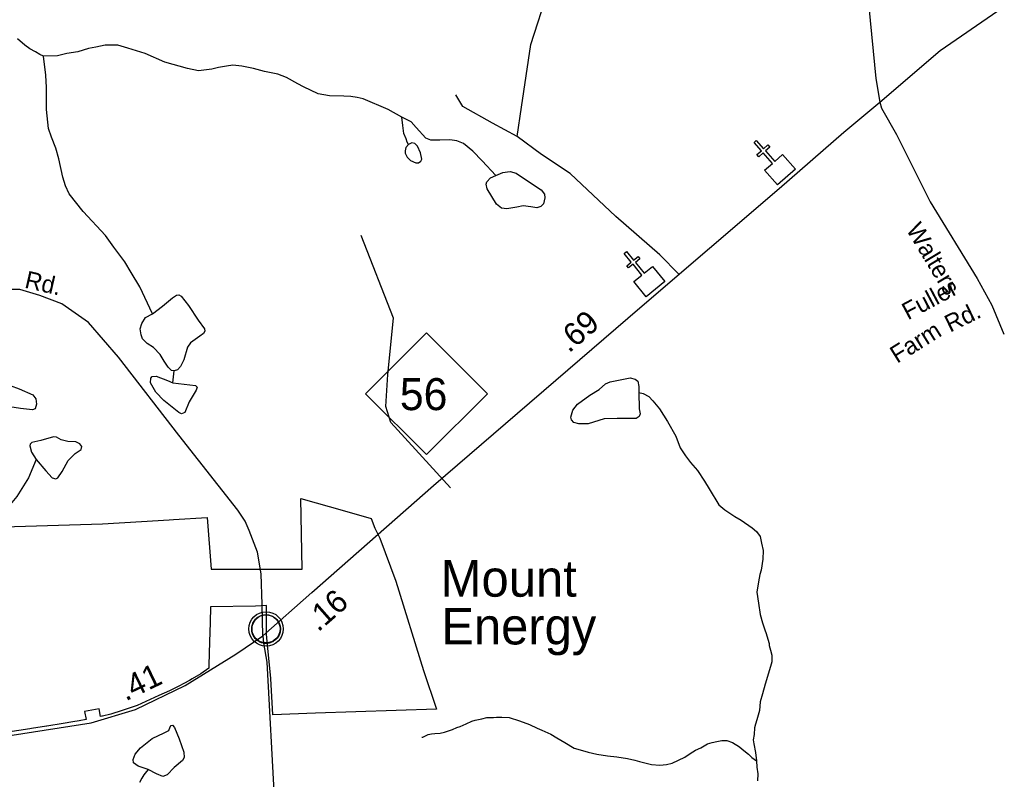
# Model space of a CAD drawing. Extents: x 2056842 to 2160602, y 826753 to 1016856.
# Drawn here: x 2104548 to 2109914, y 863916 to 868070 of the extents above; entities that cross this region are included whole.
import ezdxf

# ---------------------------------------------------------------- set-up
doc = ezdxf.new("R2010")
doc.units = 0
for name, color, linetype in [('Exist Boundary Political City Limit New', 7, 'Continuous'), ('Exist Civil Demographics Community CELL', 7, 'Continuous'), ('Exist Civil Demographics Community Label', 7, 'Continuous'), ('Exist Cultural Church CELL', 7, 'Continuous'), ('Exist Hydrographic Creek Single Shore', 7, 'Continuous'), ('Exist Hydrographic Misc Water Feature', 7, 'Continuous'), ('Exist Road Non-System Type 51', 7, 'Continuous'), ('Exist Road Non-System Type 51 Label', 7, 'Continuous'), ('Exist Road Primary NC Attributed', 7, 'Continuous'), ('Exist Road Primary NC Service Mileage Hundredths English Label', 7, 'Continuous'), ('Exist Road Primary NC Shield CELL', 7, 'Continuous'), ('Exist Road Primary NC Shield Number Label', 7, 'Continuous'), ('Exist Road Secondary Type 51 Attributed', 7, 'Continuous'), ('Exist Road Secondary Type 51 Label', 7, 'Continuous'), ('Map Preparation Boundary City Limit Buffer Line', 7, 'Continuous')]:
    doc.layers.add(name, color=color, linetype=linetype)

msp = doc.modelspace()

# ---------------------------------------------------------------- linework, layer by layer
at = {"layer": 'Exist Boundary Political City Limit New'}
msp.add_lwpolyline([(2104459, 865295.8), (2105000, 865313.7), (2105214, 865326.4), (2105366, 865335.5), (2105389.8, 865336.9), (2105573, 865347.9), (2105594, 865065.2), (2105890.8, 865065.7), (2106093, 865066.1), (2106084.2, 865451.1), (2106323.2, 865383.9), (2106469.8, 865342.6), (2106490.2, 865290.2), (2106517, 865233.9), (2106603.8, 865000), (2106755.2, 864511.2), (2106826, 864299.9), (2106165.5, 864277.4), (2105931.5, 864269.4), (2105921.2, 864466.5), (2105900.2, 864669.2), (2105898, 864709.4), (2105897.2, 864786.2), (2105898, 864865.7), (2105838, 864863.8), (2105591.8, 864859.1), (2105589.2, 864774.2), (2105586.2, 864667.2), (2105582.5, 864540.2), (2105582, 864524.1), (2105538, 864492.1), (2105491.2, 864465), (2105476, 864456.1), (2105445.5, 864440.2), (2105417.8, 864425.9), (2105400.8, 864417), (2105367.2, 864399.8), (2105309, 864373.6), (2105190.5, 864320.3), (2105174.2, 864314.6), (2105108.8, 864291.6), (2105046.8, 864273.1), (2105000, 864261.3), (2104997.2, 864260.6), (2104989.8, 864259.1), (2104981.8, 864301), (2104902.8, 864286.2), (2104910.8, 864243.2), (2104872.8, 864236.2), (2104838, 864230.1), (2104785, 864220.8), (2104696.8, 864206.1), (2104695.5, 864205.9), (2104612.8, 864193.2), (2104604, 864191.9), (2104168.2, 864126)], dxfattribs=at)
at = {"layer": 'Exist Civil Demographics Community CELL'}
msp.add_lwpolyline([(2105817.4, 864750.7), (2105818.4, 864756.3), (2105820.2, 864762.9), (2105823.1, 864770.1), (2105826, 864775.8), (2105829.4, 864781.6), (2105833.1, 864786.7), (2105837.1, 864791.1), (2105841.7, 864795.6), (2105847.2, 864800.2), (2105852.6, 864803.9), (2105857.5, 864806.8), (2105862.6, 864809.2), (2105868, 864811.5), (2105873.7, 864813.3), (2105878, 864814.5), (2105882.8, 864815.2), (2105887, 864815.9), (2105893.3, 864816.2), (2105897.8, 864816.1), (2105903.4, 864815.8), (2105908.3, 864815.1), (2105913.2, 864814.1), (2105918.2, 864812.7), (2105923.4, 864810.8), (2105930.1, 864807.9), (2105936.3, 864804.4), (2105941.4, 864800.8), (2105946.6, 864796.8), (2105949.9, 864793.7), (2105954, 864789.3), (2105957.9, 864784.6), (2105960.9, 864780), (2105964.1, 864775), (2105966.5, 864769.8), (2105968.5, 864764.8), (2105970.1, 864759.8), (2105971.4, 864755.2), (2105972.5, 864749.2), (2105973.1, 864744.5), (2105973.4, 864738.5), (2105973.2, 864732.7), (2105972.6, 864727), (2105971.7, 864721.5), (2105970, 864715.3), (2105968.2, 864709.5), (2105965.9, 864704.4), (2105962.7, 864698.4), (2105959.4, 864693.1), (2105956, 864688.4), (2105951.7, 864683.7), (2105946.5, 864678.7), (2105941.4, 864674.6), (2105936.4, 864671.1), (2105932.1, 864668.6), (2105925.3, 864665.4), (2105918.1, 864662.7), (2105912.2, 864661.2), (2105905.6, 864659.9), (2105901.2, 864659.5), (2105896.7, 864659.2), (2105891.1, 864659.2), (2105886.8, 864659.6), (2105881.2, 864660.3), (2105875.3, 864661.7), (2105870.7, 864663), (2105865.5, 864664.8), (2105860.9, 864666.8), (2105857, 864669.1), (2105850.2, 864673.1), (2105844.6, 864677.4), (2105839.7, 864681.9), (2105835.2, 864686.8), (2105832, 864690.7), (2105829.1, 864694.9), (2105825, 864702), (2105823.3, 864705.5), (2105821.5, 864709.6), (2105819, 864717.7), (2105817.4, 864724.8), (2105816.7, 864730), (2105816.4, 864736.3), (2105816.3, 864741), (2105816.9, 864747.4)], close=True, dxfattribs=at)
for centre, radius in [((2105895, 864738.3), 94.3), ((2105894.8, 864738.6), 76.7)]:
    msp.add_circle(centre, radius, dxfattribs=at)
at = {"layer": 'Exist Cultural Church CELL'}
for points in [[(2108620.2, 867246.4), (2108662.9, 867284.1), (2108612.7, 867341.3), (2108588.6, 867320.1), (2108578.1, 867332.1), (2108602.1, 867353.3), (2108562.4, 867398.4), (2108574.4, 867409), (2108614.1, 867363.8), (2108638.2, 867385), (2108648.7, 867373), (2108624.7, 867351.8), (2108675, 867294.7), (2108718.3, 867332.6), (2108788.6, 867252.7), (2108690.5, 867166.5)], [(2107905.3, 866637.3), (2107949.3, 866673.4), (2107901.2, 866732.4), (2107876.4, 866712.2), (2107866.3, 866724.6), (2107891.1, 866744.8), (2107853.1, 866791.4), (2107865.5, 866801.5), (2107903.5, 866754.9), (2107928.3, 866775.1), (2107938.4, 866762.8), (2107913.6, 866742.5), (2107961.7, 866683.5), (2108006.5, 866719.9), (2108073.8, 866637.4), (2107972.5, 866554.8)]]:
    msp.add_lwpolyline(points, close=True, dxfattribs=at)
at = {"layer": 'Exist Hydrographic Creek Single Shore'}
for points in [[(2107932.1, 866031.7), (2107955.5, 866025.7), (2107987.3, 866009.5), (2108009.6, 865985.8), (2108045.7, 865941.8), (2108089.6, 865871.9), (2108134.1, 865792.1), (2108158.5, 865728.4), (2108188, 865684.5), (2108214.5, 865648.5), (2108252.6, 865604.5), (2108291, 865546.8), (2108316.6, 865504.7), (2108369.1, 865416.9), (2108403.1, 865389), (2108457.1, 865353.2), (2108491.3, 865333.4), (2108551.4, 865291.5), (2108575.8, 865271.6), (2108595.3, 865243.8), (2108603.7, 865207.6), (2108612.1, 865167.8), (2108610, 865119.9), (2108600.4, 865059.7), (2108594.2, 865035.8), (2108586.7, 864995.6), (2108576.6, 864939.5), (2108587.1, 864880), (2108594.9, 864817.8), (2108609, 864771.9), (2108621.3, 864734), (2108628.7, 864714.2), (2108637.7, 864681.9), (2108645.3, 864658.1)], [(2108645.3, 864658.1), (2108645.3, 864648.3), (2108651.3, 864622.3), (2108659.3, 864594.2), (2108659, 864578), (2108659.3, 864558.1), (2108651.5, 864532.2), (2108645.7, 864510.2), (2108635.7, 864478.2), (2108623.6, 864436.1), (2108608.2, 864384.1), (2108596.1, 864340.1), (2108592.4, 864292), (2108578, 864242.1), (2108570.3, 864218.3), (2108564.3, 864198), (2108562.7, 864161.8), (2108556.7, 864131.8), (2108560.8, 864110.1), (2108571.1, 864061.9), (2108574.8, 864017.9)], [(2108574.8, 864017.9), (2108577.2, 863982.2), (2108583.2, 863946), (2108581.5, 863908.1)]]:
    msp.add_lwpolyline(points, dxfattribs=at)
at = {"layer": 'Exist Hydrographic Misc Water Feature'}
for points in [[(2104678, 867871), (2104658.1, 867878.9), (2104634.1, 867894.7), (2104604.3, 867910.6), (2104575.8, 867930.7), (2104535.9, 867964.3)], [(2106637.4, 867536.8), (2106562, 867579.4), (2106426.6, 867636.5), (2106393.3, 867644.8), (2106358.1, 867649.6), (2106319.2, 867650.9), (2106241.4, 867653.3), (2106180.6, 867664.2), (2106100.4, 867703.4), (2106068.2, 867719.2), (2106006.3, 867752.9), (2105959.9, 867771), (2105886.1, 867786.6), (2105825.8, 867802.7), (2105761.9, 867816.4), (2105714.1, 867820.4), (2105678.2, 867816.1), (2105634.3, 867808.1), (2105598, 867799.8), (2105526.3, 867789.5), (2105466.2, 867803.6), (2105342.1, 867837), (2105234.1, 867884.6), (2105139.5, 867914.3), (2105084, 867930), (2105015.9, 867929.8), (2104963.6, 867919.9), (2104923.6, 867911.8), (2104865.8, 867893.7), (2104806.1, 867885.3), (2104754.2, 867871.3), (2104678, 867871)], [(2105274.4, 866461.2), (2105204.3, 866608.9), (2105157.8, 866686.6), (2105123.5, 866746.5), (2105063.3, 866826.2), (2105016.9, 866890.1), (2104894.9, 867021.8), (2104818.6, 867117.4), (2104798.3, 867161.4), (2104784.2, 867209.3), (2104761.6, 867309.3), (2104745.4, 867367.4), (2104721.8, 867427), (2104705.6, 867474.9), (2104695.4, 867579.2), (2104694.4, 867698.9), (2104690.5, 867766.9), (2104678, 867871)], [(2106673.9, 867387.2), (2106666.6, 867400.6), (2106660.5, 867418.8), (2106648.3, 867446.8), (2106642.3, 867490.6), (2106637.4, 867536.8)], [(2107150.8, 867218), (2107075.4, 867298.3), (2107025.6, 867350.6), (2106974.6, 867393.2), (2106937.6, 867407.9), (2106899.9, 867412.7), (2106845.2, 867410.3), (2106795.4, 867411.5), (2106768.7, 867421.3), (2106715.2, 867479.6), (2106688.5, 867511.2), (2106637.4, 867536.8)], [(2106673.9, 867387.2), (2106658.1, 867370.2), (2106654.4, 867353.1), (2106655.6, 867339.8), (2106665.4, 867317.9), (2106684.8, 867299.6), (2106712.8, 867286.3), (2106727.3, 867287.5), (2106740.7, 867296), (2106746.8, 867306.9), (2106739.5, 867341), (2106722.5, 867377.5), (2106707.9, 867392.1), (2106690.9, 867395.7), (2106673.9, 867387.2)], [(2107150.8, 867218), (2107189.7, 867233.8), (2107214, 867238.7), (2107229.8, 867239.9), (2107261.4, 867230.2), (2107329.5, 867185.2), (2107398.8, 867140.2), (2107417, 867115.9), (2107419.4, 867095.2), (2107412.1, 867063.6), (2107397.5, 867049), (2107374.4, 867041.7), (2107342.8, 867046.6), (2107300.3, 867051.4), (2107266.3, 867044.1), (2107211.6, 867035.6), (2107182.4, 867039.3), (2107154.4, 867061.2), (2107103.4, 867145.1), (2107097.3, 867170.6), (2107101, 867184), (2107121.6, 867204.7), (2107150.8, 867218)], [(2105274.4, 866461.2), (2105329.1, 866503.8), (2105383.8, 866548.8), (2105405.7, 866563.4), (2105417.8, 866564.6), (2105431.2, 866558.5), (2105470.1, 866506.2), (2105523.6, 866427.2), (2105558.8, 866379.8), (2105560, 866366.4), (2105552.7, 866354.2), (2105533.3, 866338.4), (2105482.3, 866301.9), (2105465.2, 866278.8), (2105444.6, 866210.7), (2105427.6, 866173), (2105410.5, 866154.8), (2105392.3, 866148.9)], [(2105392.3, 866148.9), (2105377.7, 866152.3), (2105359.5, 866169.4), (2105338.8, 866202.2), (2105315.7, 866238.7), (2105279.3, 866276.4), (2105245.2, 866299.5), (2105219.7, 866325), (2105212.4, 866345.7), (2105207.6, 866378.5), (2105216.1, 866409), (2105236.7, 866440.6), (2105274.4, 866461.2)], [(2105386.2, 866084.5), (2105447, 866076), (2105509, 866069.9), (2105517.5, 866060.2), (2105512.6, 866043.1), (2105473.7, 865979.9), (2105450.7, 865922.7), (2105433.6, 865914.2), (2105417.8, 865921.5), (2105336.4, 865987.2), (2105292.6, 866032.2), (2105263.5, 866084.5), (2105264.7, 866108.8), (2105273.2, 866118.5), (2105295.1, 866121), (2105355.8, 866096.7), (2105386.2, 866084.5)], [(2105386.2, 866084.5), (2105392.3, 866148.9)], [(2107932.1, 866031.7), (2107934.5, 865941.7), (2107939.4, 865915), (2107934.5, 865900.4), (2107918.7, 865889.4), (2107893.2, 865888.2), (2107814.2, 865889.4), (2107743.7, 865887), (2107655, 865860.2), (2107603.9, 865860.2), (2107577.2, 865867.5), (2107565.1, 865882.1), (2107561.4, 865896.7), (2107572.3, 865934.4), (2107597.9, 865967.3), (2107664.7, 866017.1), (2107715.8, 866047.5), (2107749.8, 866077.9), (2107775.3, 866090.1), (2107813, 866096.2), (2107885.9, 866110.8), (2107912.7, 866104.7), (2107927.3, 866092.5), (2107933.3, 866063.3), (2107932.1, 866031.7)], [(2104638, 865665.4), (2104595.5, 865564.5), (2104532.3, 865462.3), (2104477.6, 865396.7), (2104407.6, 865342.7), (2104338.3, 865303.7), (2104288.4, 865294), (2104185.1, 865319.5), (2104133.1, 865330.5), (2104072.2, 865363.5), (2104035.7, 865397.4), (2104004, 865425), (2103956, 865471.2), (2103895.7, 865530.7), (2103826.8, 865607.8), (2103779.4, 865644.4), (2103709.1, 865714.3), (2103658.6, 865773.9), (2103608.6, 865818), (2103522.7, 865883.8), (2103446.6, 865959.5), (2103398.2, 866031.2), (2103351.9, 866084.9)], [(2104458.4, 866044.4), (2104469.3, 866061.4), (2104480.2, 866067.5), (2104496, 866068.7), (2104545.9, 866051.7), (2104620, 866017.6), (2104635.8, 865996.9), (2104639.5, 865967.7), (2104633.4, 865942.2), (2104617.6, 865937.3), (2104552, 865944.6), (2104493.6, 865953.1), (2104454.7, 865961.7), (2104443.8, 865970.2), (2104442.6, 865988.4), (2104449.9, 866021.3), (2104458.4, 866044.4)], [(2104638, 865665.4), (2104690.3, 865603.4), (2104725.5, 865564.5), (2104745, 865558.4), (2104755.9, 865564.5), (2104780.2, 865599.7), (2104813, 865659.3), (2104850.7, 865698.3), (2104884.7, 865718.9), (2104888.4, 865736), (2104877.4, 865750.5), (2104855.6, 865761.5), (2104811.8, 865763.9), (2104774.1, 865772.4), (2104749.8, 865787), (2104732.8, 865788.2), (2104663.5, 865768.8), (2104614.9, 865757.8), (2104606.4, 865749.3), (2104604, 865739.6), (2104612.5, 865704.3), (2104638, 865665.4)], [(2106747.1, 864146.3), (2106751, 864146.5), (2106763.1, 864152.3), (2106781, 864160.6), (2106799, 864164.3), (2106816.9, 864166.6), (2106847, 864168.8), (2106871, 864174.6), (2106914.9, 864189), (2106937, 864199.1), (2106955.1, 864204.8), (2106988.9, 864219.2), (2107018.8, 864233.3), (2107038.5, 864239.3), (2107074.6, 864247.2), (2107102.5, 864253.5), (2107138.6, 864253.3), (2107154.8, 864255.8), (2107184.5, 864255.7), (2107224.5, 864254.1), (2107280.5, 864235.9), (2107334.6, 864216.3), (2107376.9, 864196.1), (2107402.9, 864184.5), (2107451.1, 864162.6), (2107484.7, 864142.9), (2107528.8, 864116.8), (2107579, 864086.8), (2107611, 864077.1), (2107654.9, 864065.2), (2107703.1, 864053.4), (2107760.9, 864045.4), (2107813, 864039.5), (2107871, 864030), (2107911.4, 864020.2), (2107935.4, 864014.1), (2107965.6, 864006.3), (2108001.2, 863998), (2108047.4, 863994.3), (2108083.5, 863996.6), (2108115.2, 864004.7), (2108149.1, 864020.7), (2108183.1, 864037.1), (2108213.3, 864056.9), (2108243, 864075), (2108270.9, 864089.1), (2108308.6, 864109.4), (2108333, 864117.5), (2108359.1, 864123.2), (2108386.9, 864127.5), (2108412.8, 864127.6), (2108444.8, 864117.6), (2108482.9, 864093.9), (2108497.1, 864081.6), (2108531.1, 864053.7), (2108549.3, 864036), (2108574.8, 864017.9)], [(2105250, 863969.2), (2105195.6, 863988.2), (2105170.3, 864005.9), (2105167.7, 864023.7), (2105179.1, 864052.8), (2105209.5, 864088.3), (2105271.6, 864139), (2105338.7, 864170.6), (2105362.7, 864183.3), (2105371.6, 864203.6), (2105375.4, 864211.2), (2105383, 864212.4), (2105394.4, 864199.8), (2105419.7, 864137.7), (2105446.3, 864064.2), (2105447.6, 864036.3), (2105438.7, 864019.9), (2105393.1, 863980.6), (2105353.9, 863941.3), (2105331.1, 863932.4), (2105296.9, 863946.4), (2105250, 863969.2)], [(2105250, 863969.2), (2105234.1, 863949.8), (2105225.9, 863939.8), (2105216.2, 863921.7), (2105202.3, 863899.5)]]:
    msp.add_lwpolyline(points, dxfattribs=at)
at = {"layer": 'Exist Road Non-System Type 51'}
for points in [[(2107266.9, 867430.2), (2107291.6, 867591.8), (2107342.9, 867934.1), (2107438.9, 868235.5), (2107528.3, 868492.5), (2107711.9, 868893.9), (2107793.3, 869021.7), (2107865.5, 869084.5), (2107907.3, 869354.5)], [(2107266.9, 867430.2), (2107132, 867504.3), (2106970.5, 867595.6), (2106932.5, 867658.3)], [(2108151.2, 866678.2), (2108047, 866784.6), (2107807.5, 866993.8), (2107556.7, 867229.6), (2107399.9, 867333.2), (2107266.9, 867430.2)], [(2106903, 865510.6), (2106789, 865636.1), (2106576.2, 865868.1), (2106549.6, 865955.5), (2106561, 866130.5), (2106591.4, 866438.5), (2106414.7, 866889.2)]]:
    msp.add_lwpolyline(points, dxfattribs=at)
at = {"layer": 'Exist Road Primary NC Attributed'}
for points in [[(2109249.3, 867618.8), (2109579.9, 867901.2), (2109895.4, 868117.9), (2110256.4, 868273.9), (2110579.4, 868319.5), (2110883.5, 868319.5), (2112063.5, 868336.6), (2113120, 868348), (2113344.2, 868367), (2113701.4, 868424.1), (2113938.9, 868502), (2114239.2, 868612.3), (2114596.4, 868802.5), (2115166.5, 869224.6), (2115632, 869545.9), (2116350.3, 869990.9), (2116836.7, 870298.9), (2117092.3, 870412.1), (2117523.6, 870543.3), (2117945.5, 870645.9), (2118948.8, 870876), (2119491.3, 870989.2), (2119985.3, 871048.1), (2120520.2, 871060.5)], [(2105876.5, 864701), (2106145.4, 864937.7), (2106810.4, 865523.4), (2107937.2, 866495), (2108699.2, 867147.2), (2109052.6, 867455.3), (2109249.3, 867618.8)], [(2102996.9, 863927.9), (2103550.1, 864016.7), (2104131.7, 864099.8), (2104938.5, 864225.6), (2105181.5, 864298.3), (2105453.6, 864429.3), (2105729.8, 864599.7), (2105876.5, 864701)]]:
    msp.add_lwpolyline(points, dxfattribs=at)
at = {"layer": 'Exist Road Primary NC Shield CELL'}
msp.add_lwpolyline([(2106438.9, 866024.5), (2106771.9, 866357.5), (2107104.9, 866024.5), (2106771.9, 865691.5)], close=True, dxfattribs=at)
at = {"layer": 'Exist Road Secondary Type 51 Attributed'}
for points in [[(2109955.7, 871740.7), (2109790.4, 871478.3), (2109470.2, 870965.9), (2109291.6, 870682.5), (2109229.8, 870529.5), (2109193.7, 870394.5), (2109174.7, 870238.6), (2109176.6, 869860.2), (2109173.8, 868718.3), (2109189.9, 868139.3), (2109227.9, 867747.6), (2109249.3, 867618.8)], [(2109249.3, 867618.8), (2109258.1, 867585.3), (2109341.5, 867442.4), (2109525.5, 867074.2), (2109781.3, 866655.2), (2109861.8, 866509.4), (2109927, 866350.2)], [(2105876.5, 864701), (2105873.2, 864871.7), (2105867.5, 865040), (2105848.5, 865157.9), (2105803.3, 865277.2), (2105780.5, 865327.6), (2105740.6, 865388.4), (2105418.1, 865797.7), (2105087.9, 866225.1), (2104923.6, 866414.2), (2104778.7, 866515.5), (2104659, 866561.1), (2104548.7, 866594.4), (2104440.4, 866594.4), (2103979.2, 866623.4), (2103854.7, 866638.6), (2103785.3, 866655.7), (2103696, 866689), (2103284.2, 866999.4), (2102968.7, 867253.6)], [(2105876.5, 864701), (2105881.4, 864661), (2105898.6, 864556.6), (2105941.2, 863784.5), (2105957.8, 863472.7), (2105972.3, 863179.7), (2105996.2, 863016.5), (2106060.6, 862713.1), (2106240.2, 861805.9), (2106283.8, 861571), (2106296.3, 861423.5), (2106275.5, 861269.7), (2106174.8, 860805.2), (2106100, 860468.5), (2105980.6, 859920.8), (2105945.3, 859746.2), (2105901.7, 859505.2), (2105874.7, 859326.4), (2105849.8, 859105.6)]]:
    msp.add_lwpolyline(points, dxfattribs=at)
at = {"layer": 'Map Preparation Boundary City Limit Buffer Line'}
msp.add_lwpolyline([(2104459, 865295.8), (2105000, 865313.7), (2105214, 865326.4), (2105366, 865335.5), (2105389.8, 865336.9), (2105573, 865347.9), (2105594, 865065.2), (2105890.8, 865065.7), (2106093, 865066.1), (2106084.2, 865451.1), (2106323.2, 865383.9), (2106469.8, 865342.6), (2106490.2, 865290.2), (2106517, 865233.9), (2106603.8, 865000), (2106755.2, 864511.2), (2106826, 864299.9), (2106165.5, 864277.4), (2105931.5, 864269.4), (2105921.2, 864466.5), (2105900.2, 864669.2), (2105898, 864709.4), (2105897.2, 864786.2), (2105898, 864865.7), (2105838, 864863.8), (2105591.8, 864859.1), (2105589.2, 864774.2), (2105586.2, 864667.2), (2105582.5, 864540.2), (2105582, 864524.1), (2105538, 864492.1), (2105491.2, 864465), (2105476, 864456.1), (2105445.5, 864440.2), (2105417.8, 864425.9), (2105400.8, 864417), (2105367.2, 864399.8), (2105309, 864373.6), (2105190.5, 864320.3), (2105174.2, 864314.6), (2105108.8, 864291.6), (2105046.8, 864273.1), (2105000, 864261.3), (2104997.2, 864260.6), (2104989.8, 864259.1), (2104981.8, 864301), (2104902.8, 864286.2), (2104910.8, 864243.2), (2104872.8, 864236.2), (2104838, 864230.1), (2104785, 864220.8), (2104696.8, 864206.1), (2104695.5, 864205.9), (2104612.8, 864193.2), (2104604, 864191.9), (2104168.2, 864126)], dxfattribs=at)

# ---------------------------------------------------------------- texts
at = {"layer": 'Exist Civil Demographics Community Label'}
for s, p in [('Mount', (2106849.7, 864914.8)), ('Energy', (2106852.7, 864653.7))]:
    msp.add_text(s, height=200, dxfattribs=at).set_placement(p)
at = {"layer": 'Exist Road Non-System Type 51 Label'}
for s, rotation, p in [('Fuller', 27.9952, (2109403.4, 866425)), ('Rd.', 26.1894, (2109633.8, 866358.1)), ('Farm', 32.0218, (2109344.1, 866187.8))]:
    msp.add_text(s, height=95, rotation=rotation, dxfattribs=at).set_placement(p)
at = {"layer": 'Exist Road Primary NC Service Mileage Hundredths English Label'}
for s, rotation, p in [('.69', 40.7713, (2107550.3, 866243.9)), ('.16', 41.367, (2106179.6, 864718.1)), ('.41', 25.6992, (2105127.4, 864341.6))]:
    msp.add_text(s, height=125, rotation=rotation, dxfattribs=at).set_placement(p)
at = {"layer": 'Exist Road Primary NC Shield Number Label'}
msp.add_text('56', height=175, dxfattribs=at).set_placement((2106626, 865934.8))
at = {"layer": 'Exist Road Secondary Type 51 Label'}
for s, rotation, p in [('Walters', 301.0778, (2109390.7, 866923.1)), ('Rd.', 347.1982, (2104570.6, 866605.1))]:
    msp.add_text(s, height=95, rotation=rotation, dxfattribs=at).set_placement(p)

doc.saveas('drawing.dxf')
